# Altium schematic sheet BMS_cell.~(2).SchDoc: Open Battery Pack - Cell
size A4; Date: 26/03/2019; Author: Morgane Vallée - Samuel Lesueur; Revision: 1.0; SheetNumber: 3; SheetTotal: 3
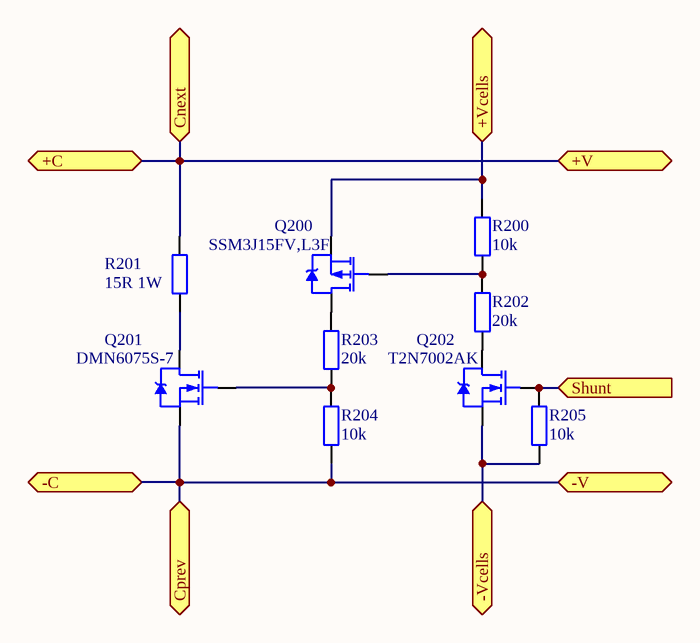
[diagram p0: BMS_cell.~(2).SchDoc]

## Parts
Q200  SSM3J15FV,L3F  [DIODES SOT-23-3]
Q201  DMN6075S-7  [DIODES SOT-23-3]
Q202  T2N7002AK  [DIODES SOT-23-3]
R200  10k  [R0603]
R201  15R 1W  [STACKPOLE CSR2512]
R202  20k  [R0603]
R203  20k  [R0603]
R204  10k  [R0603]
R205  10k  [R0603]

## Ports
+C, +V, +Vcells, -C, -V, -Vcells, Cnext, Cprev, Shunt (in)

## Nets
+C: R201.2 ; port +C, port Cnext, port +V
+Vcells: Q200.2(S) R200.2 ; port +Vcells
-C: Q201.2(S) R204.1 ; port -C, port Cprev, port -V
-Vcells: Q202.2(S) R205.1 ; port -Vcells
Shunt: Q202.1(G) R205.2 ; port Shunt
NetQ200_1: Q200.1(G) R200.1 R202.2
NetQ200_3: Q200.3(D) R203.2
NetQ201_1: Q201.1(G) R203.1 R204.2
NetQ201_3: Q201.3(D) R201.1
NetQ202_3: Q202.3(D) R202.1

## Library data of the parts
Q200 = MOSFET_P
Q201 Q202 = MOSFET_N
R200-R205 = Res2: Resistor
